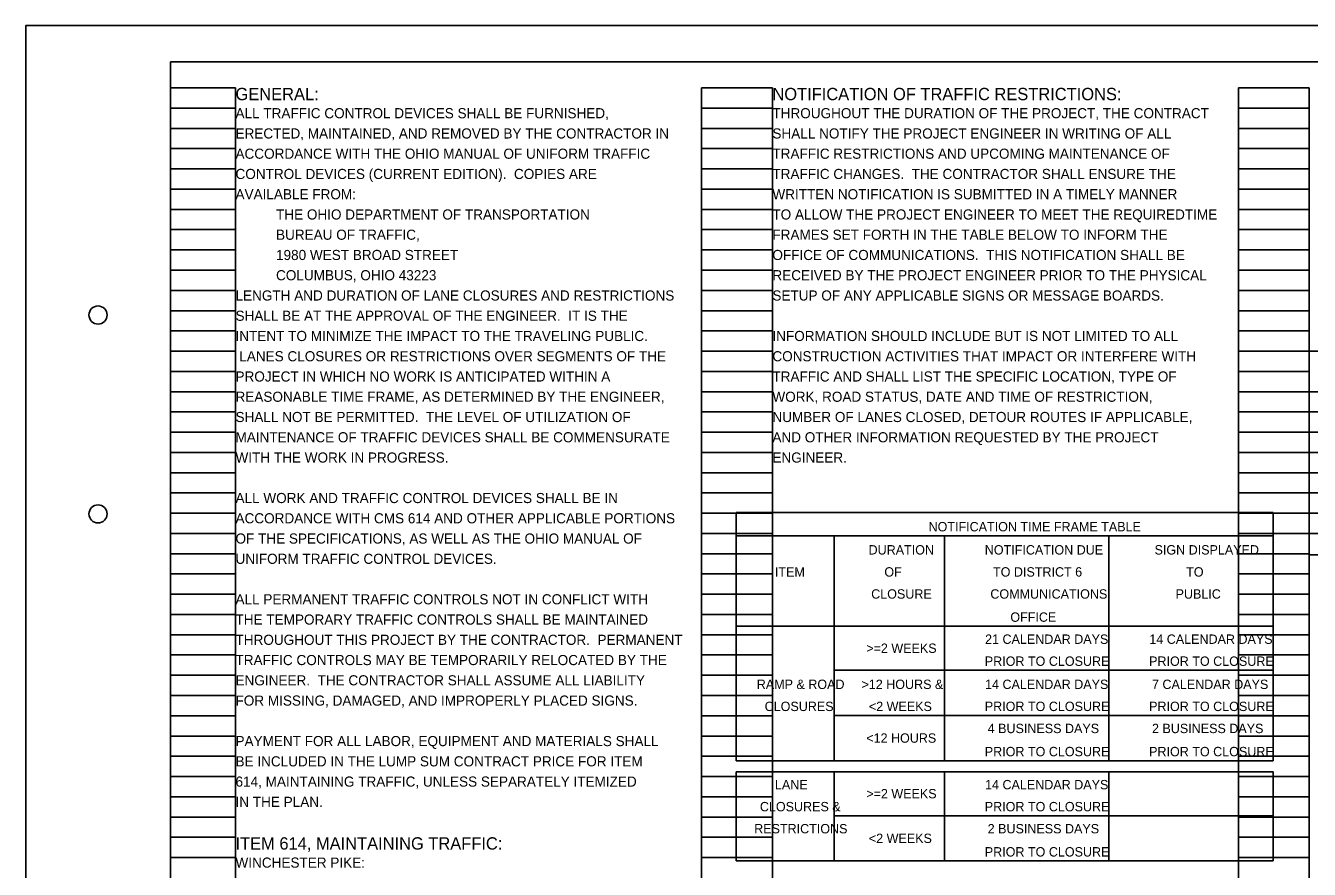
# Model space of a CAD drawing. Extents: x 0 to 34, y 0 to 22.
# Drawn here: x 0 to 17.74, y 10.34 to 22 of the extents above; entities that cross this region are included whole.
import ezdxf

# ---------------------------------------------------------------- set-up
doc = ezdxf.new("R2010")
doc.units = 0
for name, color, linetype in [('BD_P_Text', 7, 'Continuous'), ('SH_Border', 7, 'Continuous'), ('SH_Cut_Line', 7, 'Continuous'), ('SH_Data', 7, 'Continuous'), ('SH_Text', 7, 'Continuous')]:
    doc.layers.add(name, color=color, linetype=linetype)

msp = doc.modelspace()

# ---------------------------------------------------------------- linework, layer by layer
at = {"layer": 'SH_Border'}
msp.add_lwpolyline([(2, 21.5), (33.5, 21.5), (33.5, 0.5), (2, 0.5)], close=True, dxfattribs=at)
for centre in [(1, 18), (1, 15.25)]:
    msp.add_circle(centre, 0.125, dxfattribs=at)
at = {"layer": 'SH_Cut_Line'}
msp.add_lwpolyline([(0, 0), (34, 0), (34, 22), (0, 22)], close=True, dxfattribs=at)
at = {"layer": 'SH_Data'}
for p, q in [((2, 0.98), (2, 21.14)), ((2, 21.14), (2.9, 21.14)), ((2.9, 0.98), (2.9, 21.14)), ((9.34, 0.98), (9.34, 21.14)), ((9.34, 21.14), (10.32, 21.14)), ((10.32, 0.98), (10.32, 21.14)), ((16.76, 0.98), (16.76, 21.14)), ((16.76, 21.14), (17.74, 21.14)), ((17.74, 0.98), (17.74, 21.14)), ((2, 20.86), (2.9, 20.86)), ((9.34, 20.86), (10.32, 20.86)), ((16.76, 20.86), (17.74, 20.86)), ((2, 20.58), (2.9, 20.58)), ((9.34, 20.58), (10.32, 20.58)), ((16.76, 20.58), (17.74, 20.58)), ((2, 20.3), (2.9, 20.3)), ((9.34, 20.3), (10.32, 20.3)), ((16.76, 20.3), (17.74, 20.3)), ((2, 20.02), (2.9, 20.02)), ((9.34, 20.02), (10.32, 20.02)), ((16.76, 20.02), (17.74, 20.02)), ((2, 19.74), (2.9, 19.74)), ((9.34, 19.74), (10.32, 19.74)), ((16.76, 19.74), (17.74, 19.74)), ((2, 19.46), (2.9, 19.46)), ((9.34, 19.46), (10.32, 19.46)), ((16.76, 19.46), (17.74, 19.46)), ((2, 19.18), (2.9, 19.18)), ((9.34, 19.18), (10.32, 19.18)), ((16.76, 19.18), (17.74, 19.18)), ((2, 18.9), (2.9, 18.9)), ((9.34, 18.9), (10.32, 18.9)), ((16.76, 18.9), (17.74, 18.9)), ((2, 18.62), (2.9, 18.62)), ((9.34, 18.62), (10.32, 18.62)), ((16.76, 18.62), (17.74, 18.62)), ((2, 18.34), (2.9, 18.34)), ((9.34, 18.34), (10.32, 18.34)), ((16.76, 18.34), (17.74, 18.34)), ((2, 18.06), (2.9, 18.06)), ((9.34, 18.06), (10.32, 18.06)), ((16.76, 18.06), (17.74, 18.06)), ((2, 17.78), (2.9, 17.78)), ((9.34, 17.78), (10.32, 17.78)), ((16.76, 17.78), (17.74, 17.78)), ((2, 17.5), (2.9, 17.5)), ((9.34, 17.5), (10.32, 17.5)), ((16.76, 17.5), (17.74, 17.5)), ((17.74, 17.5), (24.312, 17.5)), ((17.74, 17.5), (17.74, 14.684)), ((2, 17.22), (2.9, 17.22)), ((9.34, 17.22), (10.32, 17.22)), ((16.76, 17.22), (17.74, 17.22)), ((2, 16.94), (2.9, 16.94)), ((9.34, 16.94), (10.32, 16.94)), ((16.76, 16.94), (17.74, 16.94)), ((17.74, 16.94), (24.312, 16.94)), ((2, 16.66), (2.9, 16.66)), ((9.34, 16.66), (10.32, 16.66)), ((16.76, 16.66), (17.74, 16.66)), ((17.74, 16.66), (24.312, 16.66)), ((2, 16.38), (2.9, 16.38)), ((9.34, 16.38), (10.32, 16.38)), ((16.76, 16.38), (17.74, 16.38)), ((17.74, 16.38), (24.312, 16.38)), ((2, 16.1), (2.9, 16.1)), ((9.34, 16.1), (10.32, 16.1)), ((16.76, 16.1), (17.74, 16.1)), ((17.74, 16.1), (24.312, 16.1)), ((2, 15.82), (2.9, 15.82)), ((9.34, 15.82), (10.32, 15.82)), ((16.76, 15.82), (17.74, 15.82)), ((17.74, 15.82), (24.312, 15.82)), ((2, 15.54), (2.9, 15.54)), ((9.34, 15.54), (10.32, 15.54)), ((16.76, 15.54), (17.74, 15.54)), ((17.74, 15.54), (24.312, 15.54)), ((2, 15.26), (2.9, 15.26)), ((9.34, 15.26), (10.32, 15.26)), ((9.819, 15.268), (17.239, 15.268)), ((9.819, 15.268), (9.819, 11.839)), ((16.76, 15.26), (17.74, 15.26)), ((17.239, 15.268), (17.239, 11.839)), ((17.74, 15.26), (24.312, 15.26)), ((2, 14.98), (2.9, 14.98)), ((9.34, 14.98), (10.32, 14.98)), ((9.819, 14.948), (17.239, 14.948)), ((11.175, 14.948), (11.175, 11.839)), ((12.699, 14.948), (12.699, 11.839)), ((14.969, 14.948), (14.969, 11.839)), ((16.76, 14.98), (17.74, 14.98)), ((17.74, 14.98), (24.312, 14.98)), ((2, 14.7), (2.9, 14.7)), ((9.34, 14.7), (10.32, 14.7)), ((16.76, 14.7), (17.74, 14.7)), ((17.74, 14.684), (24.312, 14.684)), ((2, 14.42), (2.9, 14.42)), ((9.34, 14.42), (10.32, 14.42)), ((16.76, 14.42), (17.74, 14.42)), ((2, 14.14), (2.9, 14.14)), ((9.34, 14.14), (10.32, 14.14)), ((16.76, 14.14), (17.74, 14.14)), ((2, 13.86), (2.9, 13.86)), ((9.34, 13.86), (10.32, 13.86)), ((16.76, 13.86), (17.74, 13.86)), ((9.819, 13.698), (17.239, 13.698)), ((2, 13.58), (2.9, 13.58)), ((9.34, 13.58), (10.32, 13.58)), ((16.76, 13.58), (17.74, 13.58)), ((2, 13.3), (2.9, 13.3)), ((9.34, 13.3), (10.32, 13.3)), ((16.76, 13.3), (17.74, 13.3)), ((2, 13.02), (2.9, 13.02)), ((9.34, 13.02), (10.32, 13.02)), ((11.175, 13.089), (17.239, 13.089)), ((16.76, 13.02), (17.74, 13.02)), ((2, 12.74), (2.9, 12.74)), ((9.34, 12.74), (10.32, 12.74)), ((16.76, 12.74), (17.74, 12.74)), ((2, 12.46), (2.9, 12.46)), ((9.34, 12.46), (10.32, 12.46)), ((11.175, 12.464), (17.239, 12.464)), ((16.76, 12.46), (17.74, 12.46)), ((2, 12.18), (2.9, 12.18)), ((9.34, 12.18), (10.32, 12.18)), ((16.76, 12.18), (17.74, 12.18)), ((2, 11.9), (2.9, 11.9)), ((9.34, 11.9), (10.32, 11.9)), ((16.76, 11.9), (17.74, 11.9)), ((9.819, 11.839), (17.239, 11.839)), ((2, 11.62), (2.9, 11.62)), ((9.34, 11.62), (10.32, 11.62)), ((9.819, 11.687), (17.239, 11.687)), ((9.819, 11.687), (9.819, 10.453)), ((11.175, 11.687), (11.175, 10.453)), ((12.699, 11.687), (12.699, 10.453)), ((14.969, 11.687), (14.969, 10.453)), ((16.76, 11.62), (17.74, 11.62)), ((17.239, 11.687), (17.239, 10.453)), ((2, 11.34), (2.9, 11.34)), ((9.34, 11.34), (10.32, 11.34)), ((16.76, 11.34), (17.74, 11.34)), ((2, 11.06), (2.9, 11.06)), ((9.34, 11.06), (10.32, 11.06)), ((11.175, 11.078), (17.239, 11.078)), ((16.76, 11.06), (17.74, 11.06)), ((2, 10.78), (2.9, 10.78)), ((9.34, 10.78), (10.32, 10.78)), ((16.76, 10.78), (17.74, 10.78)), ((2, 10.5), (2.9, 10.5)), ((9.34, 10.5), (10.32, 10.5)), ((16.76, 10.5), (17.74, 10.5)), ((9.819, 10.453), (17.239, 10.453))]:
    msp.add_line(p, q, dxfattribs=at)

# ---------------------------------------------------------------- texts
at = {"layer": 'BD_P_Text'}
for s, height, p in [('GENERAL:', 0.17, (2.9, 20.97)), ('NOTIFICATION OF TRAFFIC RESTRICTIONS:', 0.17, (10.32, 20.97)), ('ALL TRAFFIC CONTROL DEVICES SHALL BE FURNISHED, ', 0.14, (2.9, 20.72)), ('THROUGHOUT THE DURATION OF THE PROJECT, THE CONTRACT ', 0.14, (10.32, 20.72)), ('ERECTED, MAINTAINED, AND REMOVED BY THE CONTRACTOR IN ', 0.14, (2.9, 20.44)), ('SHALL NOTIFY THE PROJECT ENGINEER IN WRITING OF ALL ', 0.14, (10.32, 20.44)), ('ACCORDANCE WITH THE OHIO MANUAL OF UNIFORM TRAFFIC ', 0.14, (2.9, 20.16)), ('TRAFFIC RESTRICTIONS AND UPCOMING MAINTENANCE OF ', 0.14, (10.32, 20.16)), ('CONTROL DEVICES (CURRENT EDITION).  COPIES ARE ', 0.14, (2.9, 19.88)), ('TRAFFIC CHANGES.  THE CONTRACTOR SHALL ENSURE THE ', 0.14, (10.32, 19.88)), ('AVAILABLE FROM:', 0.14, (2.9, 19.6)), ('WRITTEN NOTIFICATION IS SUBMITTED IN A TIMELY MANNER ', 0.14, (10.32, 19.6)), ('THE OHIO DEPARTMENT OF TRANSPORTATION', 0.14, (3.46, 19.32)), ('TO ALLOW THE PROJECT ENGINEER TO MEET THE REQUIREDTIME ', 0.14, (10.32, 19.32)), ('BUREAU OF TRAFFIC,', 0.14, (3.46, 19.04)), ('FRAMES SET FORTH IN THE TABLE BELOW TO INFORM THE ', 0.14, (10.32, 19.04)), ('1980 WEST BROAD STREET', 0.14, (3.46, 18.76)), ('OFFICE OF COMMUNICATIONS.  THIS NOTIFICATION SHALL BE ', 0.14, (10.32, 18.76)), ('COLUMBUS, OHIO 43223 ', 0.14, (3.46, 18.48)), ('RECEIVED BY THE PROJECT ENGINEER PRIOR TO THE PHYSICAL ', 0.14, (10.32, 18.48)), ('LENGTH AND DURATION OF LANE CLOSURES AND RESTRICTIONS ', 0.14, (2.9, 18.2)), ('SETUP OF ANY APPLICABLE SIGNS OR MESSAGE BOARDS.', 0.14, (10.32, 18.2)), ('SHALL BE AT THE APPROVAL OF THE ENGINEER.  IT IS THE ', 0.14, (2.9, 17.92)), ('INTENT TO MINIMIZE THE IMPACT TO THE TRAVELING PUBLIC. ', 0.14, (2.9, 17.64)), ('INFORMATION SHOULD INCLUDE BUT IS NOT LIMITED TO ALL ', 0.14, (10.32, 17.64)), (' LANES CLOSURES OR RESTRICTIONS OVER SEGMENTS OF THE ', 0.14, (2.9, 17.36)), ('CONSTRUCTION ACTIVITIES THAT IMPACT OR INTERFERE WITH ', 0.14, (10.32, 17.36)), ('PROJECT IN WHICH NO WORK IS ANTICIPATED WITHIN A ', 0.14, (2.9, 17.08)), ('TRAFFIC AND SHALL LIST THE SPECIFIC LOCATION, TYPE OF ', 0.14, (10.32, 17.08)), ('REASONABLE TIME FRAME, AS DETERMINED BY THE ENGINEER, ', 0.14, (2.9, 16.8)), ('WORK, ROAD STATUS, DATE AND TIME OF RESTRICTION, ', 0.14, (10.32, 16.8)), ('SHALL NOT BE PERMITTED.  THE LEVEL OF UTILIZATION OF ', 0.14, (2.9, 16.52)), ('NUMBER OF LANES CLOSED, DETOUR ROUTES IF APPLICABLE, ', 0.14, (10.32, 16.52)), ('MAINTENANCE OF TRAFFIC DEVICES SHALL BE COMMENSURATE ', 0.14, (2.9, 16.24)), ('AND OTHER INFORMATION REQUESTED BY THE PROJECT ', 0.14, (10.32, 16.24)), ('WITH THE WORK IN PROGRESS.', 0.14, (2.9, 15.96)), ('ENGINEER.', 0.14, (10.32, 15.96)), ('ALL WORK AND TRAFFIC CONTROL DEVICES SHALL BE IN ', 0.14, (2.9, 15.4)), ('ACCORDANCE WITH CMS 614 AND OTHER APPLICABLE PORTIONS ', 0.14, (2.9, 15.12)), ('OF THE SPECIFICATIONS, AS WELL AS THE OHIO MANUAL OF ', 0.14, (2.9, 14.84)), ('UNIFORM TRAFFIC CONTROL DEVICES.', 0.14, (2.9, 14.56)), ('ALL PERMANENT TRAFFIC CONTROLS NOT IN CONFLICT WITH ', 0.14, (2.9, 14)), ('THE TEMPORARY TRAFFIC CONTROLS SHALL BE MAINTAINED ', 0.14, (2.9, 13.72)), ('THROUGHOUT THIS PROJECT BY THE CONTRACTOR.  PERMANENT ', 0.14, (2.9, 13.44)), ('TRAFFIC CONTROLS MAY BE TEMPORARILY RELOCATED BY THE ', 0.14, (2.9, 13.16)), ('ENGINEER.  THE CONTRACTOR SHALL ASSUME ALL LIABILITY ', 0.14, (2.9, 12.88)), ('FOR MISSING, DAMAGED, AND IMPROPERLY PLACED SIGNS.', 0.14, (2.9, 12.6)), ('PAYMENT FOR ALL LABOR, EQUIPMENT AND MATERIALS SHALL ', 0.14, (2.9, 12.04)), ('BE INCLUDED IN THE LUMP SUM CONTRACT PRICE FOR ITEM ', 0.14, (2.9, 11.76)), ('614, MAINTAINING TRAFFIC, UNLESS SEPARATELY ITEMIZED ', 0.14, (2.9, 11.48)), ('IN THE PLAN.', 0.14, (2.9, 11.2)), ('ITEM 614, MAINTAINING TRAFFIC:', 0.17, (2.9, 10.61)), ('WINCHESTER PIKE:', 0.14, (2.9, 10.36))]:
    msp.add_text(s, height=height, dxfattribs=at).set_placement(p)
at = {"layer": 'SH_Text'}
for s, height, p in [('NOTIFICATION TIME FRAME TABLE', 0.12951, (12.478, 15.009)), ('DURATION', 0.1295, (11.649, 14.689)), ('NOTIFICATION DUE', 0.12951, (13.255, 14.689)), ('SIGN DISPLAYED', 0.12951, (15.601, 14.689)), ('ITEM', 0.1295, (10.355, 14.384)), ('OF', 0.1295, (11.867, 14.384)), ('TO DISTRICT 6', 0.12951, (13.369, 14.384)), ('TO', 0.1295, (16.038, 14.384)), ('CLOSURE', 0.1295, (11.685, 14.079)), ('COMMUNICATIONS', 0.12951, (13.332, 14.079)), ('PUBLIC', 0.1295, (15.892, 14.079)), (' OFFICE', 0.1295, (13.56, 13.759)), ('21 CALENDAR DAYS', 0.12951, (13.259, 13.454)), ('14 CALENDAR DAYS', 0.12951, (15.529, 13.454)), ('>=2 WEEKS', 0.1295, (11.617, 13.329)), ('PRIOR TO CLOSURE', 0.12951, (13.255, 13.15)), ('PRIOR TO CLOSURE', 0.12951, (15.526, 13.15)), ('RAMP & ROAD', 0.12951, (10.104, 12.83)), ('>12 HOURS &', 0.12951, (11.551, 12.83)), ('14 CALENDAR DAYS', 0.12951, (13.259, 12.83)), ('7 CALENDAR DAYS', 0.12951, (15.566, 12.83)), ('CLOSURES', 0.1295, (10.213, 12.525)), ('<2 WEEKS', 0.1295, (11.653, 12.525)), ('PRIOR TO CLOSURE', 0.12951, (13.255, 12.525)), ('PRIOR TO CLOSURE', 0.12951, (15.526, 12.525)), ('4 BUSINESS DAYS', 0.12951, (13.295, 12.22)), ('2 BUSINESS DAYS', 0.12951, (15.566, 12.22)), ('<12 HOURS', 0.1295, (11.617, 12.087)), ('PRIOR TO CLOSURE', 0.12951, (13.255, 11.9)), ('PRIOR TO CLOSURE', 0.12951, (15.526, 11.9)), ('LANE', 0.1295, (10.355, 11.443)), ('14 CALENDAR DAYS', 0.12951, (13.259, 11.443)), ('>=2 WEEKS', 0.1295, (11.617, 11.318)), ('CLOSURES &', 0.1295, (10.147, 11.139)), ('PRIOR TO CLOSURE', 0.12951, (13.255, 11.139)), ('RESTRICTIONS', 0.12951, (10.068, 10.834)), ('<2 WEEKS', 0.1295, (11.653, 10.701)), ('2 BUSINESS DAYS', 0.12951, (13.295, 10.834)), ('PRIOR TO CLOSURE', 0.12951, (13.255, 10.514))]:
    msp.add_text(s, height=height, dxfattribs=at).set_placement(p)

doc.saveas('drawing.dxf')
